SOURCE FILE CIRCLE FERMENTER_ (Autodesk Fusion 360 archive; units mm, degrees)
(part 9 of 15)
hole "Foratura1" HoleDepth 12 named "d1132_1" HoleDiameter 3.5 named "d1133_1" TipAngle 180 named "d1134_1"
position "Posizione1"
sketch "Schizzo4" plane through (-180, 0, 0) normal (1, 0, 0) x axis (0, 1, 0)
  line L1 (-36.4, -31.9) -> (36.4, -31.9)
  line L2 (-42.9, 53.4) -> (-42.9, -25.4)
  line L3 (36.4, 59.9) -> (-36.4, 59.9)
  line L4 (42.9, -25.4) -> (42.9, 53.4)
  line L5 (65, -86.5) -> (-65, -86.5)
  curve K1 (88, -63.5) -> (65, -86.5)
  line L6 (88, -56.2402) -> (88, -63.5)
  line L7 (79.4522, -45.6213) -> (86.5355, -52.7047)
  line L8 (86.5355, -34.2953) -> (79.4522, -41.3787)
  line L9 (88, 58.7598) -> (88, -30.7598)
  line L10 (79.4522, 69.3787) -> (86.5355, 62.2953)
  line L11 (86.5355, 80.7047) -> (79.4522, 73.6213)
  line L12 (88, 91.5) -> (88, 84.2402)
  curve K2 (65, 114.5) -> (88, 91.5)
  line L13 (-65, 114.5) -> (65, 114.5)
  curve K3 (-65, 114.5) -> (-88, 91.5)
  line L14 (-88, 84.2402) -> (-88, 91.5)
  line L15 (-79.4522, 73.6213) -> (-86.5355, 80.7047)
  line L16 (-86.5355, 62.2953) -> (-79.4522, 69.3787)
  line L17 (-88, -30.7598) -> (-88, 58.7598)
  line L18 (-79.4522, -41.3787) -> (-86.5355, -34.2953)
  line L19 (-86.5355, -52.7047) -> (-79.4522, -45.6213)
  line L20 (-88, -63.5) -> (-88, -56.2402)
  curve K4 (-88, -63.5) -> (-65, -86.5)
  arc A1 centre (-36.4, -25.4) radius 6.5 clockwise from (-36.4, -31.9) to (-42.9, -25.4)
  arc A2 centre (-36.4, 53.4) radius 6.5 clockwise from (-42.9, 53.4) to (-36.4, 59.9)
  arc A3 centre (36.4, 53.4) radius 6.5 clockwise from (36.4, 59.9) to (42.9, 53.4)
  arc A4 centre (36.4, -25.4) radius 6.5 clockwise from (42.9, -25.4) to (36.4, -31.9)
  circle C1 centre (25, 110.9) radius 1.75
  circle C2 centre (84.4, -11) radius 1.75
  circle C3 centre (25, -82.9) radius 1.75
  circle C4 centre (84.4, 39) radius 1.75
  circle C5 centre (-84.4, 39) radius 1.75
  circle C6 centre (-25, -82.9) radius 1.75
  circle C7 centre (-84.4, -11) radius 1.75
  circle C8 centre (-25, 110.9) radius 1.75
  arc A5 centre (83, -56.2402) radius 5 clockwise from (86.5355, -52.7047) to (88, -56.2402)
  arc A6 centre (81.5735, -43.5) radius 3 clockwise from (79.4522, -45.6213) to (79.4522, -41.3787)
  arc A7 centre (83, -30.7598) radius 5 clockwise from (88, -30.7598) to (86.5355, -34.2953)
  arc A8 centre (83, 58.7598) radius 5 clockwise from (86.5355, 62.2953) to (88, 58.7598)
  arc A9 centre (81.5735, 71.5) radius 3 clockwise from (79.4522, 69.3787) to (79.4522, 73.6213)
  arc A10 centre (83, 84.2402) radius 5 clockwise from (88, 84.2402) to (86.5355, 80.7047)
  arc A11 centre (-83, 84.2402) radius 5 clockwise from (-86.5355, 80.7047) to (-88, 84.2402)
  arc A12 centre (-81.5735, 71.5) radius 3 clockwise from (-79.4522, 73.6213) to (-79.4522, 69.3787)
  arc A13 centre (-83, 58.7598) radius 5 clockwise from (-88, 58.7598) to (-86.5355, 62.2953)
  arc A14 centre (-83, -30.7598) radius 5 clockwise from (-86.5355, -34.2953) to (-88, -30.7598)
  arc A15 centre (-81.5735, -43.5) radius 3 clockwise from (-79.4522, -41.3787) to (-79.4522, -45.6213)
  arc A16 centre (-83, -56.2402) radius 5 clockwise from (-88, -56.2402) to (-86.5355, -52.7047)
  circle C9 centre (55.4256, 46) radius 1.75
  circle C10 centre (-55.4256, 46) radius 1.75
  circle C11 centre (0, -50) radius 1.75
extrude "Estrusione2" cut sketch "Schizzo4" profile of C9 C10 C11 against normal blind 49.402 named "d1135_1"
thread "Filettatura1"
sketch "Schizzo2" plane through (0, 0, -88.5) normal (0, 0, 1) x axis (-1, 0, 0)
  line L1 (124.4, -25) -> (124.4, 25)
  curve K1 (95, -54.4) -> (124.4, -25)
  line L2 (0, -54.4) -> (95, -54.4)
  line L3 (-2, -54.4) -> (0, -54.4)
  line L4 (-2, -59.7) -> (-2, -54.4)
  line L5 (0, -59.7) -> (-2, -59.7)
  line L6 (0, -65) -> (0, -59.7)
  line L7 (95, -65) -> (0, -65)
  curve K2 (95, -65) -> (135, -25)
  line L8 (135, 25) -> (135, -25)
  curve K3 (95, 65) -> (135, 25)
  line L9 (0, 65) -> (95, 65)
  line L10 (0, 59.7) -> (0, 65)
  line L11 (-2, 59.7) -> (0, 59.7)
  line L12 (-2, 54.4) -> (-2, 59.7)
  line L13 (0, 54.4) -> (-2, 54.4)
  line L14 (95, 54.4) -> (0, 54.4)
  curve K4 (95, 54.4) -> (124.4, 25)
  line L15 (124.4, 0) -> (135, 0)
  line L16 (124.4, 2) -> (135, 2)
  line L17 (135, 0) -> (135, 2)
  line L18 (124.4, 0) -> (124.4, 2)
  circle C1 centre (47.5, 60) radius 1.75
  circle C2 centre (130, 25) radius 1.75
  circle C3 centre (130, -25) radius 1.75
  circle C4 centre (47.5, -60) radius 1.75
  point P24 (135, 0)
  point P25 (124.4, 0)
  midpoint L8 P24
  midpoint L1 P25
  perpendicular L15 L17
  perpendicular L15 L18
  dimension "d1237_1" = 2
revolve "Rivoluzione1" sketch "Schizzo2" AlongAngle 360 named "d1238_1"
extrude "Estrusione2" cut of existing geometry blind -5.446 named "d1239_1"
mirror "Specchio1" mirrorStitchTolerance 0.1 named "d821_1_1"
sketch "Schizzo28" plane through (0, -90, 0) normal (0, -1, 0) x axis (1, 0, 0)
  line L1 (160, -63.5) -> (85, -63.5)
  line L2 (160, 91.5) -> (160, -63.5)
  line L3 (85, 91.5) -> (160, 91.5)
  line L4 (0, 91.5) -> (85, 91.5)
  line L5 (0, 81.5) -> (0, 91.5)
  line L6 (95, 81.5) -> (0, 81.5)
  curve K1 (125, 51.5) -> (95, 81.5)
  line L7 (125, -23.5) -> (125, 51.5)
  curve K2 (125, -23.5) -> (95, -53.5)
  line L8 (0, -53.5) -> (95, -53.5)
  line L9 (0, -63.5) -> (0, -53.5)
  line L10 (85, -63.5) -> (0, -63.5)
  line L11 (125, 14) -> (160, 14)
  line L12 (160, -23.5) -> (125, -23.5)
  line L13 (160, 51.5) -> (125, 51.5)
  circle C1 centre (47.5, -58.5) radius 3.35
  circle C2 centre (130, -23.5) radius 3.35
  circle C3 centre (130, 51.5) radius 3.35
  circle C4 centre (47.5, 86.5) radius 3.35
  point P18 (160, 14)
  point P19 (125, 14)
  point P10 (125, -23.5)
  point P20 (125, -23.5)
  point P21 (160, -23.5)
  point P9 (125, 51.5)
  point P22 (125, 51.5)
  point P23 (160, 51.5)
  midpoint L2 P18
  midpoint L7 P19
  coincident P10 P20
  coincident L2 P21
  perpendicular L2 L12
  coincident P9 P22
  coincident L2 P23
  perpendicular L2 L13
  dimension "d1247" distance L11 L12 = 37.5
extrude "Estrusione1" cut sketch "Schizzo28" profile of L2 L7 C2 C3 L11 L12 L13 against normal blind 402.391 bodies "PROFILO BASE (1)"
move "Sposta1"
combine "Combina1" bodies "PROFILO BASE"
position "Posizione2"
component_insert "Inserimento componente4"
remove_instance "RimuoviIstanza1"
remove_instance "RimuoviIstanza2"
remove_instance "RimuoviIstanza3"
remove_instance "RimuoviIstanza4"
remove_instance "RimuoviIstanza5"
remove_instance "RimuoviIstanza6"
remove_instance "RimuoviIstanza3"
remove_instance "RimuoviIstanza4"
split "Dividi1" bodies "PROFILO BASE (1) (1)"
remove_body "RimuoviCorpo1"
work_plane "Piano di lavoro1" AlongDistance -23.5
split "Dividi2" bodies "PROFILO BASE (1) (1)"
work_plane "Piano di lavoro2" AlongDistance -25
split "Dividi3" bodies "PROFILO BASE (1) (1) (1)"
work_plane "Piano di lavoro3" AlongDistance -25
split "Dividi4" bodies "PROFILO BASE (1) (1) (2)"
work_plane "Piano di lavoro4" AlongDistance -40
split "Dividi5" bodies "PROFILO BASE (1) (1) (3)"
remove_body "RimuoviCorpo2"
move "Sposta2"
extrude "Estrusione2" add of existing geometry blind 20 bodies "PROFILO BASE (1)", "PROFILO BASE (1) (1) (1)"
extrude "Estrusione3" add of existing geometry blind 20 bodies "PROFILO BASE (1) (1) (2)"
sketch "Schizzo2" plane through (0, -90, 0) normal (0, -1, 0) x axis (1, 0, 0)
  line L1 (160, 16.5) -> (160, -63.5)
  line L2 (85, 16.5) -> (160, 16.5)
  line L3 (0, 16.5) -> (85, 16.5)
  line L4 (0, 6.5) -> (0, 16.5)
  line L5 (95, 6.5) -> (0, 6.5)
  curve K1 (125, -23.5) -> (95, 6.5)
  curve K2 (125, -23.5) -> (95, -53.5)
  line L6 (0, -53.5) -> (95, -53.5)
  line L7 (0, -63.5) -> (0, -53.5)
  line L8 (85, -63.5) -> (0, -63.5)
  line L9 (160, -63.5) -> (85, -63.5)
  circle C1 centre (130, -23.5) radius 3.35
  circle C2 centre (47.5, -58.5) radius 3.35
  circle C3 centre (47.5, 11.5) radius 3.35
  circle C4 centre (139, -4) radius 1.75
  circle C5 centre (139, -12) radius 1.75
  circle C6 centre (139, -12) radius 2
  circle C7 centre (139, -4) radius 2
  concentric C5 C6
  concentric C4 C7
  dimension "d1260" diameter C6 = 4
  dimension "d1261" diameter C7 = 4
extrude "Estrusione4" cut sketch "Schizzo2" profile of C6 C7 blind -9.757 from offset -0.8
work_plane "Piano di lavoro5" AlongDistance 4
sketch "Schizzo3" plane through (0, -85.2, 0) normal (0, 1, 0) x axis (1, 0, 0)
  curve K1 (137.0635, 3.5) -> (140.9365, 3.5)
  curve K2 (140.9365, 3.5) -> (137.0635, 3.5)
  curve K3 (139.3405, 13.9708) -> (139.3405, 13.9708)
  circle C1 centre (139, 4) radius 2
  circle C2 centre (139, 12) radius 2
  circle C3 centre (139, 4) radius 2.5
  circle C4 centre (139, 12) radius 2.5
  concentric C1 C3
  concentric C2 C4
  dimension "d1266" diameter C3 = 5
  dimension "d1267" diameter C4 = 5
extrude "Estrusione5" cut sketch "Schizzo3" profile of K1 K2 K3 C3 C4 along normal blind 7.429
offset_faces "FacceDiOffset1" distance -0.25
mirror "Specchio1" mirrorStitchTolerance 0.1
sketch "Schizzo1" plane through (0, 85.4, 0) normal (0, -1, 0) x axis (1, 0, 0)
  line L1 (134.5, 51.5) -> (134.5, -23.5)
  curve K1 (95, 91) -> (134.5, 51.5)
  line L2 (-95, 91) -> (95, 91)
  curve K2 (-95, 91) -> (-134.5, 51.5)
  line L3 (-134.5, -23.5) -> (-134.5, 51.5)
  curve K3 (-134.5, -23.5) -> (-95, -63)
  line L4 (95, -63) -> (-95, -63)
  curve K4 (134.5, -23.5) -> (95, -63)
  line L5 (134.5, 51.5) -> (134.5, -23.5)
  curve K5 (95, 91) -> (134.5, 51.5)
  line L6 (-95, 91) -> (95, 91)
  curve K6 (-95, 91) -> (-134.5, 51.5)
  line L7 (-134.5, -23.5) -> (-134.5, 51.5)
  curve K7 (-134.5, -23.5) -> (-95, -63)
  line L8 (95, -63) -> (-95, -63)
  curve K8 (134.5, -23.5) -> (95, -63)
  circle C1 centre (-130, 51.5) radius 1.75
  circle C2 centre (-32, -58.5) radius 1.75
  circle C3 centre (-95, 86.5) radius 1.75
  circle C4 centre (-32, 86.5) radius 1.75
  circle C5 centre (-95, -58.5) radius 1.75
  circle C6 centre (-130, -23.5) radius 1.75
  circle C7 centre (130, -23.5) radius 1.75
  circle C8 centre (95, -58.5) radius 1.75
  circle C9 centre (32, 86.5) radius 1.75
  circle C10 centre (95, 86.5) radius 1.75
  circle C11 centre (32, -58.5) radius 1.75
  circle C12 centre (130, 51.5) radius 1.75
  circle C13 centre (-130, 51.5) radius 1.75
  circle C14 centre (-32, -58.5) radius 1.75
  circle C15 centre (-95, 86.5) radius 1.75
  circle C16 centre (-32, 86.5) radius 1.75
  circle C17 centre (-95, -58.5) radius 1.75
  circle C18 centre (-130, -23.5) radius 1.75
  circle C19 centre (130, -23.5) radius 1.75
  circle C20 centre (95, -58.5) radius 1.75
  circle C21 centre (32, 86.5) radius 1.75
  circle C22 centre (95, 86.5) radius 1.75
  circle C23 centre (32, -58.5) radius 1.75
  circle C24 centre (130, 51.5) radius 1.75
sketch "Schizzo3" plane through (0, 0, -83.9) normal (0, 0, 1) x axis (-1, 0, 0)
  line L1 (-95, 64.5) -> (95, 64.5)
  curve K1 (-134.5, 25) -> (-95, 64.5)
  line L2 (-134.5, -25) -> (-134.5, 25)
  curve K2 (-134.5, -25) -> (-95, -64.5)
  line L3 (95, -64.5) -> (-95, -64.5)
  curve K3 (134.5, -25) -> (95, -64.5)
  line L4 (134.5, 25) -> (134.5, -25)
  curve K4 (134.5, 25) -> (95, 64.5)
  circle C1 centre (130, 25) radius 1.75
  circle C2 centre (95, 60) radius 1.75
  circle C3 centre (32, 60) radius 1.75
  circle C4 centre (32, -60) radius 1.75
  circle C5 centre (95, -60) radius 1.75
  circle C6 centre (130, -25) radius 1.75
  circle C7 centre (-130, -25) radius 1.75
  circle C8 centre (-95, -60) radius 1.75
  circle C9 centre (-32, -60) radius 1.75
  circle C10 centre (-32, 60) radius 1.75
  circle C11 centre (-95, 60) radius 1.75
  circle C12 centre (-130, 25) radius 1.75
sketch "Schizzo3" plane through (0, 0, -86.9) normal (0, 0, -1) x axis (1, 0, 0)
  line L1 (-74.1572, -16.6179) -> (14.0208, -27.6401)
  line L2 (-89.206, -6.8768) -> (-81.4524, -13.4232)
  line L3 (-81.4524, 13.4232) -> (-89.206, 6.8768)
  line L4 (14.0208, 27.6401) -> (-74.1572, 16.6179)
  line L5 (90, 28.4) -> (26.2258, 28.4)
  curve K1 (98.4, 20) -> (90, 28.4)
  line L6 (98.4, -20) -> (98.4, 20)
  curve K2 (90, -28.4) -> (98.4, -20)
  line L7 (26.2258, -28.4) -> (90, -28.4)
  line L8 (95, -64.5) -> (-95, -64.5)
  curve K3 (95, -64.5) -> (134.5, -25)
  line L9 (134.5, 25) -> (134.5, -25)
  curve K4 (95, 64.5) -> (134.5, 25)
  line L10 (-95, 64.5) -> (95, 64.5)
  curve K5 (-95, 64.5) -> (-134.5, 25)
  line L11 (-134.5, -25) -> (-134.5, 25)
  curve K6 (-95, -64.5) -> (-134.5, -25)
  arc A1 centre (26.2258, 70) radius 98.4 clockwise from (26.2258, -28.4) to (14.0208, -27.6401)
  arc A2 centre (-72.4207, -2.726) radius 14 clockwise from (-74.1572, -16.6179) to (-81.4524, -13.4232)
  arc A3 centre (-83.4, 0) radius 9 clockwise from (-89.206, -6.8768) to (-89.206, 6.8768)
  arc A4 centre (-72.4207, 2.726) radius 14 clockwise from (-81.4524, 13.4232) to (-74.1572, 16.6179)
  arc A5 centre (26.2258, -70) radius 98.4 clockwise from (14.0208, 27.6401) to (26.2258, 28.4)
  circle C1 centre (-88, 16) radius 1.75
  circle C2 centre (101.9, -16) radius 1.75
  circle C3 centre (-88, -16) radius 1.75
  circle C4 centre (101.9, 16) radius 1.75
  circle C5 centre (-130, 25) radius 1.75
  circle C6 centre (-95, 60) radius 1.75
  circle C7 centre (-32, 60) radius 1.75
  circle C8 centre (-32, -60) radius 1.75
  circle C9 centre (-95, -60) radius 1.75
  circle C10 centre (-130, -25) radius 1.75
  circle C11 centre (130, -25) radius 1.75
  circle C12 centre (95, -60) radius 1.75
  circle C13 centre (32, -60) radius 1.75
  circle C14 centre (32, 60) radius 1.75
  circle C15 centre (95, 60) radius 1.75
  circle C16 centre (130, 25) radius 1.75
split "Dividi1" bodies "PROFILO BASE PORTA (1)"
remove_body "RimuoviCorpo1"
work_plane "Piano di lavoro1" AlongDistance -25
work_plane "Piano di lavoro2" AlongDistance -25
split "Dividi2" bodies "PROFILO BASE PORTA (1)"
split "Dividi3" bodies "PROFILO BASE PORTA (2)"
extrude "Estrusione1" cut of existing geometry blind -37.5
extrude "Estrusione2" cut of existing geometry blind -37.5
move "Sposta2"
move "Sposta3"
combine "Combina1" bodies "PROFILO BASE PORTA"
combine "Combina2" bodies "PROFILO BASE PORTA (1)"
sketch "Schizzo1" plane through (0, 0, 0) normal (0, 1, 0) x axis (-1, 0, 0)
  line L1 (-160, -87.7) -> (-160.8, -88.5)
  line L2 (-160, -86.4) -> (-160, -87.7)
  curve K1 (-158, -86.2311) -> (-160, -86.4)
  line L3 (-158, -81.6165) -> (-158, -86.2311)
  line L4 (-158.0208, -81.6165) -> (-158, -81.6165)
  line L5 (-162.7708, -78.5305) -> (-162.9316, -78.809)
  line L6 (-163.0684, -78.809) -> (-163.2292, -78.5305)
  line L7 (-158.4792, -81.6165) -> (-158.3184, -81.338)
  line L8 (-163.4, -78.7543) -> (-163.4, -81.4793)
  line L9 (-158.1816, -81.338) -> (-158.0208, -81.6165)
  line L10 (-158.3184, -81.338) -> (-158.1816, -81.338)
  line L11 (-162.9316, -78.809) -> (-163.0684, -78.809)
  line L12 (-158, -76.4) -> (-158, -78.809)
  curve K2 (-180, -86.9) -> (-158, -76.4)
  line L13 (-180, -88.5) -> (-180, -86.9)
  line L14 (-160.8, -88.5) -> (-180, -88.5)
  line L15 (-158, -81.6165) -> (-162.9316, -78.809)
  line L16 (-158.5208, -81.6165) -> (-158.4792, -81.6165)
  line L17 (-158.6816, -81.338) -> (-158.5208, -81.6165)
  line L18 (-158.8184, -81.338) -> (-158.6816, -81.338)
  line L19 (-158.9792, -81.6165) -> (-158.8184, -81.338)
  line L20 (-159.0208, -81.6165) -> (-158.9792, -81.6165)
  line L21 (-159.1816, -81.338) -> (-159.0208, -81.6165)
  line L22 (-159.3184, -81.338) -> (-159.1816, -81.338)
  line L23 (-159.4792, -81.6165) -> (-159.3184, -81.338)
  line L24 (-159.5208, -81.6165) -> (-159.4792, -81.6165)
  line L25 (-159.6816, -81.338) -> (-159.5208, -81.6165)
  line L26 (-159.8184, -81.338) -> (-159.6816, -81.338)
  line L27 (-159.9792, -81.6165) -> (-159.8184, -81.338)
  line L28 (-160.0208, -81.6165) -> (-159.9792, -81.6165)
  line L29 (-160.1816, -81.338) -> (-160.0208, -81.6165)
  line L30 (-160.3184, -81.338) -> (-160.1816, -81.338)
  line L31 (-160.4792, -81.6165) -> (-160.3184, -81.338)
  line L32 (-160.5208, -81.6165) -> (-160.4792, -81.6165)
  line L33 (-160.6816, -81.338) -> (-160.5208, -81.6165)
  line L34 (-160.8184, -81.338) -> (-160.6816, -81.338)
  line L35 (-160.9792, -81.6165) -> (-160.8184, -81.338)
  line L36 (-161.0208, -81.6165) -> (-160.9792, -81.6165)
  line L37 (-161.1816, -81.338) -> (-161.0208, -81.6165)
  line L38 (-161.3184, -81.338) -> (-161.1816, -81.338)
  line L39 (-161.4792, -81.6165) -> (-161.3184, -81.338)
  line L40 (-161.5208, -81.6165) -> (-161.4792, -81.6165)
  line L41 (-161.6816, -81.338) -> (-161.5208, -81.6165)
  line L42 (-161.8184, -81.338) -> (-161.6816, -81.338)
  line L43 (-161.9792, -81.6165) -> (-161.8184, -81.338)
  line L44 (-162.0208, -81.6165) -> (-161.9792, -81.6165)
  line L45 (-162.1816, -81.338) -> (-162.0208, -81.6165)
  line L46 (-162.3184, -81.338) -> (-162.1816, -81.338)
  line L47 (-162.4792, -81.6165) -> (-162.3184, -81.338)
  line L48 (-162.5208, -81.6165) -> (-162.4792, -81.6165)
  line L49 (-162.6816, -81.338) -> (-162.5208, -81.6165)
  line L50 (-162.8184, -81.338) -> (-162.6816, -81.338)
  line L51 (-162.9792, -81.6165) -> (-162.8184, -81.338)
  line L52 (-163.0208, -81.6165) -> (-162.9792, -81.6165)
  line L53 (-163.1816, -81.338) -> (-163.0208, -81.6165)
  line L54 (-163.3184, -81.338) -> (-163.1816, -81.338)
  line L55 (-163.4, -81.4793) -> (-163.3184, -81.338)
  line L56 (-163.2708, -78.5305) -> (-163.4, -78.7543)
  line L57 (-163.2292, -78.5305) -> (-163.2708, -78.5305)
  line L58 (-162.7292, -78.5305) -> (-162.7708, -78.5305)
  line L59 (-162.5684, -78.809) -> (-162.7292, -78.5305)
  line L60 (-162.4316, -78.809) -> (-162.5684, -78.809)
  line L61 (-162.2708, -78.5305) -> (-162.4316, -78.809)
  line L62 (-162.2292, -78.5305) -> (-162.2708, -78.5305)
  line L63 (-162.0684, -78.809) -> (-162.2292, -78.5305)
  line L64 (-161.9316, -78.809) -> (-162.0684, -78.809)
  line L65 (-161.7708, -78.5305) -> (-161.9316, -78.809)
  line L66 (-161.7292, -78.5305) -> (-161.7708, -78.5305)
  line L67 (-161.5684, -78.809) -> (-161.7292, -78.5305)
  line L68 (-161.4316, -78.809) -> (-161.5684, -78.809)
  line L69 (-161.2708, -78.5305) -> (-161.4316, -78.809)
  line L70 (-161.2292, -78.5305) -> (-161.2708, -78.5305)
  line L71 (-161.0684, -78.809) -> (-161.2292, -78.5305)
  line L72 (-160.9316, -78.809) -> (-161.0684, -78.809)
  line L73 (-160.7708, -78.5305) -> (-160.9316, -78.809)
  line L74 (-160.7292, -78.5305) -> (-160.7708, -78.5305)
  line L75 (-160.5684, -78.809) -> (-160.7292, -78.5305)
  line L76 (-160.4316, -78.809) -> (-160.5684, -78.809)
  line L77 (-160.2708, -78.5305) -> (-160.4316, -78.809)
  line L78 (-160.2292, -78.5305) -> (-160.2708, -78.5305)
  line L79 (-160.0684, -78.809) -> (-160.2292, -78.5305)
  line L80 (-159.9316, -78.809) -> (-160.0684, -78.809)
  line L81 (-159.7708, -78.5305) -> (-159.9316, -78.809)
  line L82 (-159.7292, -78.5305) -> (-159.7708, -78.5305)
  line L83 (-159.5684, -78.809) -> (-159.7292, -78.5305)
  line L84 (-159.4316, -78.809) -> (-159.5684, -78.809)
  line L85 (-159.2708, -78.5305) -> (-159.4316, -78.809)
  line L86 (-159.2292, -78.5305) -> (-159.2708, -78.5305)
  line L87 (-159.0684, -78.809) -> (-159.2292, -78.5305)
  line L88 (-158.9316, -78.809) -> (-159.0684, -78.809)
  line L89 (-158.7708, -78.5305) -> (-158.9316, -78.809)
  line L90 (-158.7292, -78.5305) -> (-158.7708, -78.5305)
  line L91 (-158.5684, -78.809) -> (-158.7292, -78.5305)
  line L92 (-158.4316, -78.809) -> (-158.5684, -78.809)
  line L93 (-158.2708, -78.5305) -> (-158.4316, -78.809)
  line L94 (-158.2292, -78.5305) -> (-158.2708, -78.5305)
  line L95 (-158.0684, -78.809) -> (-158.2292, -78.5305)
  line L96 (-158, -78.809) -> (-158.0684, -78.809)
  point P18 (-162.9316, -78.809)
  point P22 (-162.9316, -78.809)
  point P6 (-158, -81.6165)
  point P23 (-158, -81.6165)
  coincident P18 P22
  coincident P6 P23
extrude "Estrusione3" cut sketch "Schizzo1" profile of L1 L2 K1 L3 L4 L5 L6 L7 L8 L9 L10 L11 L12 K2 L13 L14 L15 against normal blind 10
extrude "Estrusione4" add of existing geometry blind 10
sketch "Schizzo2" plane through (0, 0, 0) normal (0, 1, 0) x axis (-1, 0, 0)
  curve K1 (-158, 29.4) -> (-180, 39.9)
  line L1 (-158, 31.809) -> (-158, 29.4)
  line L2 (-158.0684, 31.809) -> (-158, 31.809)
  line L3 (-163.1816, 34.338) -> (-163.0208, 34.6165)
  line L4 (-158.2708, 31.5305) -> (-158.4316, 31.809)
  line L5 (-163.4, 34.4793) -> (-163.4, 31.7543)
  line L6 (-158.0684, 31.809) -> (-158.2292, 31.5305)
  line L7 (-158.2708, 31.5305) -> (-158.2292, 31.5305)
  line L8 (-162.9792, 34.6165) -> (-163.0208, 34.6165)
  line L9 (-158, 39.2311) -> (-158, 34.6165)
  curve K2 (-160, 39.4) -> (-158, 39.2311)
  line L10 (-160, 40.7) -> (-160, 39.4)
  line L11 (-160.8, 41.5) -> (-160, 40.7)
  line L12 (-180, 41.5) -> (-160.8, 41.5)
  line L13 (-180, 39.9) -> (-180, 41.5)
  line L14 (-158, 31.809) -> (-162.9792, 34.6165)
  line L15 (-158.5684, 31.809) -> (-158.4316, 31.809)
  line L16 (-158.5684, 31.809) -> (-158.7292, 31.5305)
  line L17 (-158.7708, 31.5305) -> (-158.7292, 31.5305)
  line L18 (-158.7708, 31.5305) -> (-158.9316, 31.809)
  line L19 (-159.0684, 31.809) -> (-158.9316, 31.809)
  line L20 (-159.0684, 31.809) -> (-159.2292, 31.5305)
  line L21 (-159.2708, 31.5305) -> (-159.2292, 31.5305)
  line L22 (-159.2708, 31.5305) -> (-159.4316, 31.809)
  line L23 (-159.5684, 31.809) -> (-159.4316, 31.809)
  line L24 (-159.5684, 31.809) -> (-159.7292, 31.5305)
  line L25 (-159.7708, 31.5305) -> (-159.7292, 31.5305)
  line L26 (-159.7708, 31.5305) -> (-159.9316, 31.809)
  line L27 (-160.0684, 31.809) -> (-159.9316, 31.809)
  line L28 (-160.0684, 31.809) -> (-160.2292, 31.5305)
  line L29 (-160.2708, 31.5305) -> (-160.2292, 31.5305)
  line L30 (-160.2708, 31.5305) -> (-160.4316, 31.809)
  line L31 (-160.5684, 31.809) -> (-160.4316, 31.809)
  line L32 (-160.5684, 31.809) -> (-160.7292, 31.5305)
  line L33 (-160.7708, 31.5305) -> (-160.7292, 31.5305)
  line L34 (-160.7708, 31.5305) -> (-160.9316, 31.809)
  line L35 (-161.0684, 31.809) -> (-160.9316, 31.809)
  line L36 (-161.0684, 31.809) -> (-161.2292, 31.5305)
  line L37 (-161.2708, 31.5305) -> (-161.2292, 31.5305)
  line L38 (-161.2708, 31.5305) -> (-161.4316, 31.809)
  line L39 (-161.5684, 31.809) -> (-161.4316, 31.809)
  line L40 (-161.5684, 31.809) -> (-161.7292, 31.5305)
  line L41 (-161.7708, 31.5305) -> (-161.7292, 31.5305)
  line L42 (-161.7708, 31.5305) -> (-161.9316, 31.809)
  line L43 (-162.0684, 31.809) -> (-161.9316, 31.809)
  line L44 (-162.0684, 31.809) -> (-162.2292, 31.5305)
  line L45 (-162.2708, 31.5305) -> (-162.2292, 31.5305)
  line L46 (-162.2708, 31.5305) -> (-162.4316, 31.809)
  line L47 (-162.5684, 31.809) -> (-162.4316, 31.809)
  line L48 (-162.5684, 31.809) -> (-162.7292, 31.5305)
  line L49 (-162.7708, 31.5305) -> (-162.7292, 31.5305)
  line L50 (-162.7708, 31.5305) -> (-162.9316, 31.809)
  line L51 (-163.0684, 31.809) -> (-162.9316, 31.809)
  line L52 (-163.0684, 31.809) -> (-163.2292, 31.5305)
  line L53 (-163.2708, 31.5305) -> (-163.2292, 31.5305)
  line L54 (-163.2708, 31.5305) -> (-163.4, 31.7543)
  line L55 (-163.4, 34.4793) -> (-163.3184, 34.338)
  line L56 (-163.1816, 34.338) -> (-163.3184, 34.338)
  line L57 (-162.9792, 34.6165) -> (-162.8184, 34.338)
  line L58 (-162.6816, 34.338) -> (-162.8184, 34.338)
  line L59 (-162.6816, 34.338) -> (-162.5208, 34.6165)
  line L60 (-162.4792, 34.6165) -> (-162.5208, 34.6165)
  line L61 (-162.4792, 34.6165) -> (-162.3184, 34.338)
  line L62 (-162.1816, 34.338) -> (-162.3184, 34.338)
  line L63 (-162.1816, 34.338) -> (-162.0208, 34.6165)
  line L64 (-161.9792, 34.6165) -> (-162.0208, 34.6165)
  line L65 (-161.9792, 34.6165) -> (-161.8184, 34.338)
  line L66 (-161.6816, 34.338) -> (-161.8184, 34.338)
  line L67 (-161.6816, 34.338) -> (-161.5208, 34.6165)
  line L68 (-161.4792, 34.6165) -> (-161.5208, 34.6165)
  line L69 (-161.4792, 34.6165) -> (-161.3184, 34.338)
  line L70 (-161.1816, 34.338) -> (-161.3184, 34.338)
  line L71 (-161.1816, 34.338) -> (-161.0208, 34.6165)
  line L72 (-160.9792, 34.6165) -> (-161.0208, 34.6165)
  line L73 (-160.9792, 34.6165) -> (-160.8184, 34.338)
  line L74 (-160.6816, 34.338) -> (-160.8184, 34.338)
  line L75 (-160.6816, 34.338) -> (-160.5208, 34.6165)
  line L76 (-160.4792, 34.6165) -> (-160.5208, 34.6165)
  line L77 (-160.4792, 34.6165) -> (-160.3184, 34.338)
  line L78 (-160.1816, 34.338) -> (-160.3184, 34.338)
  line L79 (-160.1816, 34.338) -> (-160.0208, 34.6165)
  line L80 (-159.9792, 34.6165) -> (-160.0208, 34.6165)
  line L81 (-159.9792, 34.6165) -> (-159.8184, 34.338)
  line L82 (-159.6816, 34.338) -> (-159.8184, 34.338)
  line L83 (-159.6816, 34.338) -> (-159.5208, 34.6165)
  line L84 (-159.4792, 34.6165) -> (-159.5208, 34.6165)
  line L85 (-159.4792, 34.6165) -> (-159.3184, 34.338)
  line L86 (-159.1816, 34.338) -> (-159.3184, 34.338)
  line L87 (-159.1816, 34.338) -> (-159.0208, 34.6165)
  line L88 (-158.9792, 34.6165) -> (-159.0208, 34.6165)
  line L89 (-158.9792, 34.6165) -> (-158.8184, 34.338)
  line L90 (-158.6816, 34.338) -> (-158.8184, 34.338)
  line L91 (-158.6816, 34.338) -> (-158.5208, 34.6165)
  line L92 (-158.4792, 34.6165) -> (-158.5208, 34.6165)
  line L93 (-158.4792, 34.6165) -> (-158.3184, 34.338)
  line L94 (-158.1816, 34.338) -> (-158.3184, 34.338)
  line L95 (-158.1816, 34.338) -> (-158.0208, 34.6165)
  line L96 (-158, 34.6165) -> (-158.0208, 34.6165)
  point P15 (-162.9792, 34.6165)
  point P21 (-162.9792, 34.6165)
  point P4 (-158, 31.809)
  point P22 (-158, 31.809)
  coincident P15 P21
  coincident P4 P22
extrude "Estrusione5" cut sketch "Schizzo2" profile of K1 L1 L2 L3 L4 L5 L6 L7 L8 L9 K2 L10 L11 L12 L13 L14 against normal blind 10
extrude "Estrusione6" add of existing geometry blind 10
mirror "Specchio1" mirrorStitchTolerance 0.1
sketch "Schizzo2" plane through (158, 0, 0) normal (1, 0, 0) x axis (0, 1, 0)
  line L1 (86.7, 91.3) -> (86.7, -63.3)
  line L2 (82.7, 91.3) -> (86.7, 91.3)
  curve K1 (64.8, 109.2) -> (82.7, 91.3)
  line L3 (64.8, 113.2) -> (64.8, 109.2)
  line L4 (-64.8, 113.2) -> (64.8, 113.2)
  line L5 (-64.8, 109.2) -> (-64.8, 113.2)
  curve K2 (-82.7, 91.3) -> (-64.8, 109.2)
  line L6 (-86.7, 91.3) -> (-82.7, 91.3)
  line L7 (-86.7, -63.3) -> (-86.7, 91.3)
  line L8 (-82.7, -63.3) -> (-86.7, -63.3)
  curve K3 (-64.8, -81.2) -> (-82.7, -63.3)
  line L9 (-64.8, -85.2) -> (-64.8, -81.2)
  line L10 (64.8, -85.2) -> (-64.8, -85.2)
  line L11 (64.8, -81.2) -> (64.8, -85.2)
  curve K4 (82.7, -63.3) -> (64.8, -81.2)
  line L12 (86.7, -63.3) -> (82.7, -63.3)
  line L13 (-86.7, 14) -> (86.7, 14)
  line L14 (-86.7, 4) -> (86.7, 4)
  line L15 (-86.7, 24) -> (86.7, 24)
  line L16 (-86.7, -33.5) -> (86.7, -33.5)
  line L17 (-86.7, 61.5) -> (86.7, 61.5)
  circle C1 centre (81.5735, 14) radius 1.75
  circle C2 centre (-81.5735, 14) radius 1.75
  circle C3 centre (-81.5735, 71.5) radius 1.75
  circle C4 centre (-45, 108.0735) radius 1.75
  circle C5 centre (45, 108.0735) radius 1.75
  circle C6 centre (81.5735, 71.5) radius 1.75
  circle C7 centre (0, 108.0735) radius 1.75
  circle C8 centre (0, -80.0735) radius 1.75
  circle C9 centre (81.5735, -43.5) radius 1.75
  circle C10 centre (45, -80.0735) radius 1.75
  circle C11 centre (-45, -80.0735) radius 1.75
  circle C12 centre (-81.5735, -43.5) radius 1.75
  point P30 (86.7, 14)
  point P31 (-86.7, 14)
  point P32 (86.7, 4)
  point P33 (-86.7, 4)
  point P34 (86.7, 24)
  point P35 (-86.7, 24)
  midpoint L1 P30
  midpoint L7 P31
  coincident L1 P32
  coincident L7 P33
  perpendicular L7 L14
  symmetric L13 P32 P34
  symmetric L13 P33 P35
  dimension "d1287" distance L13 L14 = 10
  dimension "d1288" = -37.5
  dimension "d1289" = 37.5
extrude "Estrusione1" cut sketch "Schizzo2" profile of L1 L7 L14 L15 L16 L17 against normal blind 27.972 bodies "ACRILICO SPORTELLO (1)", "ACRILICO SPORTELLO (2)"
move "Sposta1"
move "Sposta2"
combine "Combina1" bodies "ACRILICO SPORTELLO", "ACRILICO SPORTELLO (1)"
sketch "Schizzo3" plane through (155, 0, 0) normal (-1, 0, 0) x axis (0, -1, 0)
  line L1 (-86.7, -63.3) -> (-86.7, 16.3)
  line L2 (-82.7, -63.3) -> (-86.7, -63.3)
  curve K1 (-82.7, -63.3) -> (-64.8, -81.2)
  line L3 (-64.8, -85.2) -> (-64.8, -81.2)
  line L4 (64.8, -85.2) -> (-64.8, -85.2)
  line L5 (64.8, -81.2) -> (64.8, -85.2)
  curve K2 (64.8, -81.2) -> (82.7, -63.3)
  line L6 (86.7, -63.3) -> (82.7, -63.3)
  line L7 (86.7, 16.3) -> (86.7, -63.3)
  line L8 (82.7, 16.3) -> (86.7, 16.3)
  curve K3 (82.7, 16.3) -> (64.8, 34.2)
  line L9 (64.8, 38.2) -> (64.8, 34.2)
  line L10 (-64.8, 38.2) -> (64.8, 38.2)
  line L11 (-64.8, 34.2) -> (-64.8, 38.2)
  curve K4 (-64.8, 34.2) -> (-82.7, 16.3)
  line L12 (-86.7, 16.3) -> (-82.7, 16.3)
  circle C1 centre (-45, 33.0735) radius 1.75
  circle C2 centre (-81.5735, -3.5) radius 1.75
  circle C3 centre (81.5735, -3.5) radius 1.75
  circle C4 centre (45, 33.0735) radius 1.75
  circle C5 centre (0, 33.0735) radius 1.75
  circle C6 centre (81.5735, -23.5) radius 1.75
  circle C7 centre (-81.5735, -23.5) radius 1.75
  circle C8 centre (-45, -80.0735) radius 1.75
  circle C9 centre (-81.5735, -43.5) radius 1.75
  circle C10 centre (81.5735, -43.5) radius 1.75
  circle C11 centre (45, -80.0735) radius 1.75
  circle C12 centre (0, -80.0735) radius 1.75
  circle C13 centre (0, 33.0735) radius 1.75
  circle C14 centre (0, -80.0735) radius 1.75
  circle C15 centre (81.5735, -43.5) radius 1.75
  circle C16 centre (81.5735, -3.5) radius 1.75
  circle C17 centre (-81.5735, -3.5) radius 1.75
  circle C18 centre (-81.5735, -43.5) radius 1.75
extrude "Estrusione2" add sketch "Schizzo3" profile of C2 C3 C5 L4 C9 C10 C12 C13 C14 C15 C16 C17 C18 against normal blind 3
sketch "Schizzo1" plane through (155, 0, 0) normal (1, 0, 0) x axis (0, 1, 0)
  line L1 (77.9, -63.5) -> (77.9, 91.5)
  curve K1 (65, -76.4) -> (77.9, -63.5)
  line L2 (-65, -76.4) -> (65, -76.4)
  curve K2 (-65, -76.4) -> (-77.9, -63.5)
  line L3 (-77.9, 91.5) -> (-77.9, -63.5)
  curve K3 (-65, 104.4) -> (-77.9, 91.5)
  line L4 (65, 104.4) -> (-65, 104.4)
  curve K4 (65, 104.4) -> (77.9, 91.5)
  line L5 (86.9365, 91.3) -> (86.9365, -63.3)
  line L6 (82.7, 91.3) -> (86.9365, 91.3)
  curve K5 (82.7, 91.3) -> (64.8, 109.2)
  line L7 (64.8, 113.4365) -> (64.8, 109.2)
  line L8 (-64.8, 113.4365) -> (64.8, 113.4365)
  line L9 (-64.8, 109.2) -> (-64.8, 113.4365)
  curve K6 (-64.8, 109.2) -> (-82.7, 91.3)
  line L10 (-86.9365, 91.3) -> (-82.7, 91.3)
  line L11 (-86.9365, -63.3) -> (-86.9365, 91.3)
  line L12 (-82.7, -63.3) -> (-86.9365, -63.3)
  curve K7 (-82.7, -63.3) -> (-64.8, -81.2)
  line L13 (-64.8, -85.4365) -> (-64.8, -81.2)
  line L14 (64.8, -85.4365) -> (-64.8, -85.4365)
  line L15 (64.8, -81.2) -> (64.8, -85.4365)
  curve K8 (64.8, -81.2) -> (82.7, -63.3)
  line L16 (86.9365, -63.3) -> (82.7, -63.3)
  line L17 (-86.9365, 14) -> (86.9365, 14)
  line L18 (-86.9365, 19) -> (86.9365, 19)
  line L19 (-86.9365, 56.5) -> (86.9365, 56.5)
  line L20 (-86.9365, 9) -> (86.9365, 9)
  line L21 (-86.9365, -28.5) -> (86.9365, -28.5)
  circle C1 centre (81.5735, 14) radius 1.75
  circle C2 centre (-81.5735, 14) radius 1.75
  circle C3 centre (-81.5735, 71.5) radius 1.75
  circle C4 centre (-45, 108.0735) radius 1.75
  circle C5 centre (45, 108.0735) radius 1.75
  circle C6 centre (81.5735, 71.5) radius 1.75
  circle C7 centre (0, 108.0735) radius 1.75
  circle C8 centre (0, -80.0735) radius 1.75
  circle C9 centre (81.5735, -43.5) radius 1.75
  circle C10 centre (45, -80.0735) radius 1.75
  circle C11 centre (-45, -80.0735) radius 1.75
  circle C12 centre (-81.5735, -43.5) radius 1.75
  point P38 (86.9365, 14)
  point P39 (-86.9365, 14)
  point P40 (86.9365, 19)
  point P44 (86.9365, 9)
  point P41 (-86.9365, 19)
  point P45 (-86.9365, 9)
  point P42 (86.9365, 56.5)
  point P46 (86.9365, -28.5)
  point P43 (-86.9365, 56.5)
  point P47 (-86.9365, -28.5)
  midpoint L5 P38
  midpoint L11 P39
  symmetric L17 P40 P44
  symmetric L17 P41 P45
  symmetric L17 P42 P46
  symmetric L17 P43 P47
  dimension "d1294" = 5
  dimension "d1295" = 42.5
extrude "Estrusione1" cut sketch "Schizzo1" profile of L1 L3 L5 L11 L18 L19 L20 L21 against normal blind 24.125
move "Sposta1"
move "Sposta2"
sketch "Schizzo2" plane through (151.4, 0, 0) normal (-1, 0, 0) x axis (0, -1, 0)
  line L1 (-77.9, -18.5) -> (-85.247, -18.5)
  line L2 (-77.9, 16.5) -> (-77.9, -18.5)
  curve K1 (-65, 29.4) -> (-77.9, 16.5)
  line L3 (65, 29.4) -> (-65, 29.4)
  curve K2 (65, 29.4) -> (77.9, 16.5)
  line L4 (77.9, -18.5) -> (77.9, 16.5)
  line L5 (85.247, -18.5) -> (77.9, -18.5)
  line L6 (85.247, 16.3) -> (85.247, -18.5)
  line L7 (82.7, 16.3) -> (85.247, 16.3)
  curve K3 (82.7, 16.3) -> (64.8, 34.2)
  line L8 (64.8, 36.747) -> (64.8, 34.2)
  line L9 (-64.8, 36.747) -> (64.8, 36.747)
  line L10 (-64.8, 34.2) -> (-64.8, 36.747)
  curve K4 (-64.8, 34.2) -> (-82.7, 16.3)
  line L11 (-85.247, 16.3) -> (-82.7, 16.3)
  line L12 (-85.247, -18.5) -> (-85.247, 16.3)
  line L13 (-85.247, -28.5) -> (-77.9, -28.5)
  line L14 (-85.247, -63.3) -> (-85.247, -28.5)
  line L15 (-82.7, -63.3) -> (-85.247, -63.3)
  curve K5 (-82.7, -63.3) -> (-64.8, -81.2)
  line L16 (-64.8, -83.747) -> (-64.8, -81.2)
  line L17 (64.8, -83.747) -> (-64.8, -83.747)
  line L18 (64.8, -81.2) -> (64.8, -83.747)
  curve K6 (64.8, -81.2) -> (82.7, -63.3)
  line L19 (85.247, -63.3) -> (82.7, -63.3)
  line L20 (85.247, -28.5) -> (85.247, -63.3)
  line L21 (77.9, -28.5) -> (85.247, -28.5)
  line L22 (77.9, -63.5) -> (77.9, -28.5)
  curve K7 (65, -76.4) -> (77.9, -63.5)
  line L23 (-65, -76.4) -> (65, -76.4)
  curve K8 (-65, -76.4) -> (-77.9, -63.5)
  line L24 (-77.9, -28.5) -> (-77.9, -63.5)
  circle C1 centre (81.5735, -3.5) radius 3.5
  circle C2 centre (45, 33.0735) radius 3.5
  circle C3 centre (0, 33.0735) radius 3.5
  circle C4 centre (-45, 33.0735) radius 3.5
  circle C5 centre (-81.5735, -3.5) radius 3.5
  circle C6 centre (-81.5735, -3.5) radius 1.75
  circle C7 centre (-81.5735, -3.5) radius 3.5
  circle C8 centre (-45, 33.0735) radius 3.5
  circle C9 centre (-81.5735, -43.5) radius 3.5
  circle C10 centre (-45, -80.0735) radius 3.5
  circle C11 centre (0, -80.0735) radius 3.5
  circle C12 centre (45, -80.0735) radius 3.5
  circle C13 centre (81.5735, -43.5) radius 3.5
  concentric C5 C7
extrude "Estrusione2" add sketch "Schizzo2" profile of C1 C3 C5 C6 C7 C9 C11 C13 against normal blind 3.6
combine "Combina1"
sketch "Schizzo1" plane through (0, 88.4, 0) normal (0, 1, 0) x axis (-1, 0, 0)
  line L1 (-134.5, -23.5) -> (-134.5, 51.5)
  curve K1 (-95, -63) -> (-134.5, -23.5)
  line L2 (95, -63) -> (-95, -63)
  curve K2 (95, -63) -> (134.5, -23.5)
  line L3 (134.5, 51.5) -> (134.5, -23.5)
  curve K3 (95, 91) -> (134.5, 51.5)
  line L4 (-95, 91) -> (95, 91)
  curve K4 (-95, 91) -> (-134.5, 51.5)
  line L5 (-134.5, 14) -> (134.5, 14)
  line L6 (-134.5, 51.5) -> (134.5, 51.5)
  line L7 (-134.5, -23.5) -> (134.5, -23.5)
  circle C1 centre (130, -23.5) radius 1.75
  circle C2 centre (130, 51.5) radius 1.75
  circle C3 centre (47.5, -58.5) radius 1.75
  circle C4 centre (47.5, 86.5) radius 1.75
  circle C5 centre (-47.5, 86.5) radius 1.75
  circle C6 centre (-47.5, -58.5) radius 1.75
  circle C7 centre (-130, 51.5) radius 1.75
  circle C8 centre (-130, -23.5) radius 1.75
  point P18 (134.5, 14)
  point P19 (-134.5, 14)
  midpoint L3 P18
  midpoint L1 P19
  dimension "d1300" = 37.5
  dimension "d1301" = -37.5
extrude "Estrusione6" cut sketch "Schizzo1" profile of C1 C2 C7 C8 L1 L3 L6 L7 against normal blind 3
move "Sposta1"
combine "Combina1"
joint "Assembla6" alignAngle 0 alignOffsetX 0 alignOffsetY 0 alignOffsetZ 0
remove_instance "RimuoviIstanza1"
copy_paste "CopiaIncolla3"
joint "Assembla7" alignAngle 0 alignOffsetX 0 alignOffsetY 0 alignOffsetZ 0
remove_instance "RimuoviIstanza5"
base_feature "Lavorazione di base1" bodies "PROFILO BASE"
extrude "Estrusione1" cut sketch "Schizzo28" profile of L2 L7 C2 C3 L11 L12 L13 against normal blind 402.391 named "d1248_1" bodies "PROFILO BASE (1)"
move "Sposta1"
combine "Combina1" bodies "PROFILO BASE"
position "Posizione3"
split "Dividi1" bodies "PROFILO BASE (1) (1)"
remove_body "RimuoviCorpo1"
work_plane "Piano di lavoro1" AlongDistance -23.5 named "d1250_1"
split "Dividi2" bodies "PROFILO BASE (1) (1)"
work_plane "Piano di lavoro2" AlongDistance -25 named "d1251_1"
split "Dividi3" bodies "PROFILO BASE (1) (1) (1)"
work_plane "Piano di lavoro3" AlongDistance -25 named "d1252_1"
split "Dividi4" bodies "PROFILO BASE (1) (1) (2)"
work_plane "Piano di lavoro4" AlongDistance -40 named "d1253_1"
split "Dividi5"
remove_body "RimuoviCorpo2"
move "Sposta2"
extrude "Estrusione2" add of existing geometry blind 20 named "d1254_1" bodies "PROFILO BASE (1)", "PROFILO BASE (1) (1) (1)"
extrude "Estrusione3" add of existing geometry blind 20 named "d1256_1" bodies "PROFILO BASE (1) (1) (2)"
sketch "Schizzo2" plane through (0, -90, 0) normal (0, -1, 0) x axis (1, 0, 0)
  line L1 (160, 16.5) -> (160, -63.5)
  line L2 (85, 16.5) -> (160, 16.5)
  line L3 (0, 16.5) -> (85, 16.5)
  line L4 (0, 6.5) -> (0, 16.5)
  line L5 (95, 6.5) -> (0, 6.5)
  curve K1 (125, -23.5) -> (95, 6.5)
  curve K2 (125, -23.5) -> (95, -53.5)
  line L6 (0, -53.5) -> (95, -53.5)
  line L7 (0, -63.5) -> (0, -53.5)
  line L8 (85, -63.5) -> (0, -63.5)
  line L9 (160, -63.5) -> (85, -63.5)
  circle C1 centre (130, -23.5) radius 3.35
  circle C2 centre (95, -58.5) radius 3.35
  circle C3 centre (32, -58.5) radius 3.35
  circle C4 centre (95, 11.5) radius 3.35
  circle C5 centre (32, 11.5) radius 3.35
  circle C6 centre (139, -4) radius 1.75
  circle C7 centre (139, -12) radius 1.75
  circle C8 centre (139, -12) radius 2
  circle C9 centre (139, -4) radius 2
  concentric C7 C8
  concentric C6 C9
  dimension "d1260_1" diameter C8 = 4
  dimension "d1261_1" diameter C9 = 4
extrude "Estrusione4" cut sketch "Schizzo2" profile of C8 C9 blind -9.757 named "d1263_1" from offset -0.8 named "d1262_1"
work_plane "Piano di lavoro5" AlongDistance 4 named "d1265_1"
sketch "Schizzo3" plane through (0, -85.2, 0) normal (0, 1, 0) x axis (1, 0, 0)
  curve K1 (137.0635, 3.5) -> (140.9365, 3.5)
  curve K2 (140.9365, 3.5) -> (137.0635, 3.5)
  curve K3 (139.3405, 13.9708) -> (139.3405, 13.9708)
  circle C1 centre (139, 4) radius 2
  circle C2 centre (139, 12) radius 2
  circle C3 centre (139, 4) radius 2.5
  circle C4 centre (139, 12) radius 2.5
  concentric C1 C3
  concentric C2 C4
  dimension "d1266_1" diameter C3 = 5
  dimension "d1267_1" diameter C4 = 5
extrude "Estrusione5" cut sketch "Schizzo3" profile of K1 K2 K3 C3 C4 along normal blind 7.429 named "d1268_1"
offset_faces "FacceDiOffset1" distance -0.25 named "d1270_1"
sketch "Schizzo5" plane through (0, -90, 0) normal (0, -1, 0) x axis (1, 0, 0)
  line L1 (160, 16.5) -> (160, -63.5)
  line L2 (85, 16.5) -> (160, 16.5)
  line L3 (0, 16.5) -> (85, 16.5)
  line L4 (0, 6.5) -> (0, 16.5)
  line L5 (95, 6.5) -> (0, 6.5)
  curve K1 (125, -23.5) -> (95, 6.5)
  curve K2 (125, -23.5) -> (95, -53.5)
  line L6 (0, -53.5) -> (95, -53.5)
  line L7 (0, -63.5) -> (0, -53.5)
  line L8 (85, -63.5) -> (0, -63.5)
  line L9 (160, -63.5) -> (85, -63.5)
  line L10 (0, 11.5) -> (95, 11.5)
  line L11 (69.6807, -23.5) -> (125, -23.5)
  circle C1 centre (130, -23.5) radius 3.35
  circle C2 centre (95, -58.5) radius 3.35
  circle C3 centre (32, -58.5) radius 3.35
  circle C4 centre (95, 11.5) radius 3.35
  circle C5 centre (32, 11.5) radius 3.35
  circle C6 centre (32, -58.5) radius 3.35
  circle C7 centre (95, -58.5) radius 3.35
  circle C8 centre (32, 11.5) radius 3.35
  circle C9 centre (95, 11.5) radius 3.35
  circle C10 centre (32, 11.5) radius 1.75
  circle C11 centre (47.5, 11.5) radius 1.75
  point P21 (95, 11.5)
  point P22 (95, 11.5)
  point P23 (0, 11.5)
  point P25 (47.5, 11.5)
  point P13 (125, -23.5)
  point P26 (125, -23.5)
  point P28 (47.5, -58.5)
  concentric C3 C6
  concentric C2 C7
  concentric C5 C8
  concentric C4 C9
  coincident P21 P22
  midpoint L4 P23
  coincident L10 P25
  coincident P13 P26
  horizontal L11
  symmetric P25 L11 P28
  dimension "d1439" diameter C11 = 3.5
  dimension "d1440" distance P23 P25 = 47.5 (= "( 95 / 2 ) * 1 mm")
extrude "Estrusione9" add sketch "Schizzo5" profile of C2 C3 C4 C5 C6 C7 C8 C9 C10 against normal blind 1.6
hole "Foratura1" HoleDepth 6.7 HoleDiameter 3.5 TipAngle 118 CSDiameter 6.7 CSAngle 90
sketch "Schizzo6" plane through (0, 0, 41.5) normal (0, 0, 1) x axis (-1, 0, 0)
  line L1 (-125, 0) -> (-160, 0)
  line L2 (-125, 25) -> (-125, 0)
  curve K1 (-95, 55) -> (-125, 25)
  line L3 (0, 55) -> (-95, 55)
  line L4 (0, 65) -> (0, 55)
  line L5 (-85, 65) -> (0, 65)
  line L6 (-160, 65) -> (-85, 65)
  line L7 (-160, 0) -> (-160, 65)
  line L8 (-32, 60) -> (-95, 60)
  circle C1 centre (-95, 60) radius 3.35
  circle C2 centre (-130, 25) radius 3.35
  circle C3 centre (-32, 60) radius 3.35
  circle C4 centre (-95, 60) radius 3.35
  circle C5 centre (-47.5, 60) radius 1.75
  point P2 (-95, 60)
  point P14 (-95, 60)
  point P4 (-32, 60)
  point P15 (-32, 60)
  point P16 (-47.5, 60)
  coincident P2 P14
  coincident P4 P15
  coincident L8 P16
  dimension "d1448" diameter C5 = 3.5
  dimension "d1449" distance L4 P16 = 47.5 (= "( 95 / 2 ) * 1 mm")
hole "Foratura2" HoleDepth 6.7 HoleDiameter 3.5 TipAngle 118 CSDiameter 6.7 CSAngle 90
sketch "Schizzo7" plane through (0, 0, 41.5) normal (0, 0, 1) x axis (-1, 0, 0)
  line L1 (-125, 0) -> (-160, 0)
  line L2 (-125, 25) -> (-125, 0)
  curve K1 (-95, 55) -> (-125, 25)
  line L3 (0, 55) -> (-95, 55)
  line L4 (0, 65) -> (0, 55)
  line L5 (-85, 65) -> (0, 65)
  line L6 (-160, 65) -> (-85, 65)
  line L7 (-160, 0) -> (-160, 65)
  circle C1 centre (-47.5, 60) radius 3.35
  circle C2 centre (-95, 60) radius 3.35
  circle C3 centre (-130, 25) radius 3.35
  circle C4 centre (-32, 60) radius 3.35
extrude "Estrusione10" add sketch "Schizzo7" profile of C2 C4 against normal blind 1.6
sketch "Schizzo8" plane through (0, 0, -88.5) normal (0, 0, -1) x axis (1, 0, 0)
  line L1 (85, 65) -> (160, 65)
  line L2 (0, 65) -> (85, 65)
  line L3 (0, 55) -> (0, 65)
  line L4 (95, 55) -> (0, 55)
  curve K1 (95, 55) -> (125, 25)
  line L5 (125, 0) -> (125, 25)
  line L6 (160, 0) -> (125, 0)
  line L7 (160, 65) -> (160, 0)
  line L8 (95, 60) -> (32, 60)
  circle C1 centre (32, 60) radius 3.35
  circle C2 centre (130, 25) radius 3.35
  circle C3 centre (95, 60) radius 3.35
  circle C4 centre (47.5, 60) radius 1.75
  point P10 (32, 60)
  point P13 (32, 60)
  point P12 (95, 60)
  point P14 (95, 60)
  point P15 (47.5, 60)
  coincident P10 P13
  coincident P12 P14
  dimension "d1457" diameter C4 = 3.5
  dimension "d1458" distance L3 P15 = 47.5 (= "( 95 / 2 ) * 1 mm")
hole "Foratura3" HoleDepth 6.7 HoleDiameter 3.5 TipAngle 118 CSDiameter 6.7 CSAngle 90
sketch "Schizzo9" plane through (0, 0, -88.5) normal (0, 0, -1) x axis (1, 0, 0)
  line L1 (85, 65) -> (160, 65)
  line L2 (0, 65) -> (85, 65)
  line L3 (0, 55) -> (0, 65)
  line L4 (95, 55) -> (0, 55)
  curve K1 (95, 55) -> (125, 25)
  line L5 (125, 0) -> (125, 25)
  line L6 (160, 0) -> (125, 0)
  line L7 (160, 65) -> (160, 0)
  circle C1 centre (47.5, 60) radius 3.35
  circle C2 centre (32, 60) radius 3.35
  circle C3 centre (130, 25) radius 3.35
  circle C4 centre (95, 60) radius 3.35
extrude "Estrusione11" add sketch "Schizzo9" profile of C2 C4 against normal blind 1.6
mirror "Specchio1" mirrorStitchTolerance 0.1 named "d1259_1"
extrude "Estrusione6" cut sketch "Schizzo1" profile of C1 C2 C7 C8 L1 L3 L6 L7 against normal blind 3 named "d1302_1"
joint "Assembla8" alignAngle 0 alignOffsetX 0 alignOffsetY 0 alignOffsetZ 0
sketch "Schizzo4" plane through (148.4, 0, 0) normal (1, 0, 0) x axis (0, 1, 0)
  curve K1 (-83.9651, -29.4206) -> (-79.9057, -27.4498)
  curve K2 (-79.9057, -27.4498) -> (-79.9058, -19.5505)
  curve K3 (-79.9058, -19.5505) -> (-83.9651, -17.58)
  line L1 (-83.9651, -17.58) -> (-83.9651, -18.4409)
  curve K4 (-84.564, -19.4929) -> (-83.9651, -18.4409)
  curve K5 (-83.9651, -28.5591) -> (-84.564, -27.5072)
  line L2 (-83.9651, -28.5591) -> (-83.9651, -29.4206)
  circle C1 centre (-81.5735, -23.5) radius 1
  arc A1 centre (-81.5735, -23.5) radius 5 clockwise from (-84.564, -27.5072) to (-84.564, -19.4929)
  circle C2 centre (-81.5735, -23.5) radius 1
  circle C3 centre (81.5735, -23.5) radius 1
  circle C4 centre (81.5735, -23.5) radius 2
  circle C5 centre (-81.5735, -23.5) radius 2
  concentric C3 C4
  concentric C1 C5
  dimension "d1318" diameter C4 = 4
  dimension "d1319" diameter C5 = 4
extrude "Estrusione7" cut sketch "Schizzo4" profile of C1 C2 C3 C4 C5 blind -4
extrude "Estrusione8" add of existing geometry blind 1.8
split "Dividi1"
remove_body "RimuoviCorpo1"
split "Dividi2"
remove_body "RimuoviCorpo2"
work_plane "Piano di lavoro2" AlongDistance -25
split "Dividi3"
move "Sposta1"
extrude "Estrusione4" add of existing geometry blind 20
work_plane "Piano di lavoro3"
split "Dividi4"
remove_body "RimuoviCorpo3"
mirror "Specchio3" mirrorStitchTolerance 0.1
mirror "Specchio4" mirrorStitchTolerance 0.1
sketch "Schizzo9" plane through (-153.8, 0, 0) normal (-1, 0, 0) x axis (0, -1, 0)
  line L1 (-10.25, -63.8607) -> (10.25, -63.8607)
  line L2 (-10.25, -49.3607) -> (-10.25, -63.8607)
  line L3 (10.25, -49.3607) -> (-10.25, -49.3607)
  line L4 (10.25, -63.8607) -> (10.25, -49.3607)
  line L5 (20, 10.5) -> (-20, 10.5)
  line L6 (-20, -28.5) -> (20, -28.5)
  line L7 (-20, 22.5) -> (20, 22.5)
  line L8 (20, 47.5) -> (-20, 47.5)
  line L9 (-83.1107, -63.5) -> (-83.1107, -45.4967)
  curve K1 (-65, -81.6107) -> (-83.1107, -63.5)
  line L10 (65, -81.6107) -> (-65, -81.6107)
  curve K2 (83.1107, -63.5) -> (65, -81.6107)
  line L11 (83.1107, -45.4967) -> (83.1107, -63.5)
  line L12 (83.1107, 69.5033) -> (83.1107, -41.5033)
  line L13 (83.1107, 91.5) -> (83.1107, 73.4967)
  curve K3 (65, 109.6107) -> (83.1107, 91.5)
  line L14 (-65, 109.6107) -> (65, 109.6107)
  curve K4 (-83.1107, 91.5) -> (-65, 109.6107)
  line L15 (-83.1107, 73.4967) -> (-83.1107, 91.5)
  line L16 (-83.1107, -41.5033) -> (-83.1107, 69.5033)
  line L17 (-83.1107, 14) -> (83.1107, 14)
  line L18 (-83.1107, 51.5) -> (83.1107, 51.5)
  line L19 (-83.1107, -23.5) -> (83.1107, -23.5)
  line L20 (-83.1107, 89) -> (83.1107, 89)
  line L21 (-83.1107, -61) -> (83.1107, -61)
  circle C1 centre (-12.35, -56.6107) radius 1.75
  arc A1 centre (20, -9) radius 19.5 clockwise from (20, 10.5) to (20, -28.5)
  arc A2 centre (-20, -9) radius 19.5 clockwise from (-20, -28.5) to (-20, 10.5)
  arc A3 centre (-20, 35) radius 12.5 clockwise from (-20, 22.5) to (-20, 47.5)
  arc A4 centre (20, 35) radius 12.5 clockwise from (20, 47.5) to (20, 22.5)
  circle C2 centre (-44.1, -78.7) radius 1.75
  circle C3 centre (44.1, 106.7) radius 1.75
  circle C4 centre (-44.1, 106.7) radius 1.75
  arc A5 centre (-82.6107, -41.5033) radius 0.5 clockwise from (-82.3802, -41.947) to (-83.1107, -41.5033)
  arc A6 centre (-81.5735, -43.5) radius 1.75 clockwise from (-82.3802, -41.947) to (-82.3802, -45.053)
  arc A7 centre (-82.6107, -45.4967) radius 0.5 clockwise from (-83.1107, -45.4967) to (-82.3802, -45.053)
  arc A8 centre (82.6107, -45.4967) radius 0.5 clockwise from (82.3802, -45.053) to (83.1107, -45.4967)
  arc A9 centre (81.5735, -43.5) radius 1.75 clockwise from (82.3802, -45.053) to (82.3802, -41.947)
  arc A10 centre (82.6107, -41.5033) radius 0.5 clockwise from (83.1107, -41.5033) to (82.3802, -41.947)
  arc A11 centre (82.6107, 69.5033) radius 0.5 clockwise from (82.3802, 69.947) to (83.1107, 69.5033)
  arc A12 centre (81.5735, 71.5) radius 1.75 clockwise from (82.3802, 69.947) to (82.3802, 73.053)
  arc A13 centre (82.6107, 73.4967) radius 0.5 clockwise from (83.1107, 73.4967) to (82.3802, 73.053)
  arc A14 centre (-82.6107, 73.4967) radius 0.5 clockwise from (-82.3802, 73.053) to (-83.1107, 73.4967)
  arc A15 centre (-81.5735, 71.5) radius 1.75 clockwise from (-82.3802, 73.053) to (-82.3802, 69.947)
  arc A16 centre (-82.6107, 69.5033) radius 0.5 clockwise from (-83.1107, 69.5033) to (-82.3802, 69.947)
  circle C5 centre (44.1, -78.7) radius 1.75
  circle C6 centre (0, -78.7) radius 1.75
  circle C7 centre (80.2, 14) radius 1.75
  circle C8 centre (0, 106.7) radius 1.75
  circle C9 centre (-80.2, 14) radius 1.75
  point P58 (83.1107, 14)
  point P59 (-83.1107, 14)
  midpoint L12 P58
  midpoint L16 P59
  dimension "d1331" = 37.5
  dimension "d1332" = -37.5
  dimension "d1333" = 75
  dimension "d1334" = -75
extrude "Estrusione4" cut sketch "Schizzo9" profile of C1 L2 L3 L4 L5 A1 L6 A2 A5 A6 A7 L9 L11 A8 A9 A10 L12 L16 L17 L19 L21 against normal blind 3
move "Sposta1"
combine "Combina1"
